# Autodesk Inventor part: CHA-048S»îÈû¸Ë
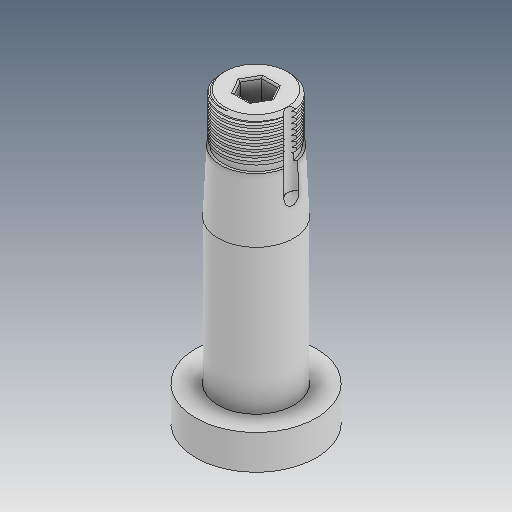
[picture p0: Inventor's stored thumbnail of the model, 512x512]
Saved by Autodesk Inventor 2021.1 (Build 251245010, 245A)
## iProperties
Created: 2019-12
Part Number: CHA-048S»îÈû¸Ë
Material: Ogólny
Document SubType Name: Modeling
Designer: user
Density: 1 g/cm^3
Appearance: Domyślna
Author: user
Revision Number: ÈÎºÎ
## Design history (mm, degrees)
feature "ÊäÈë1"
node "Bryła1"
